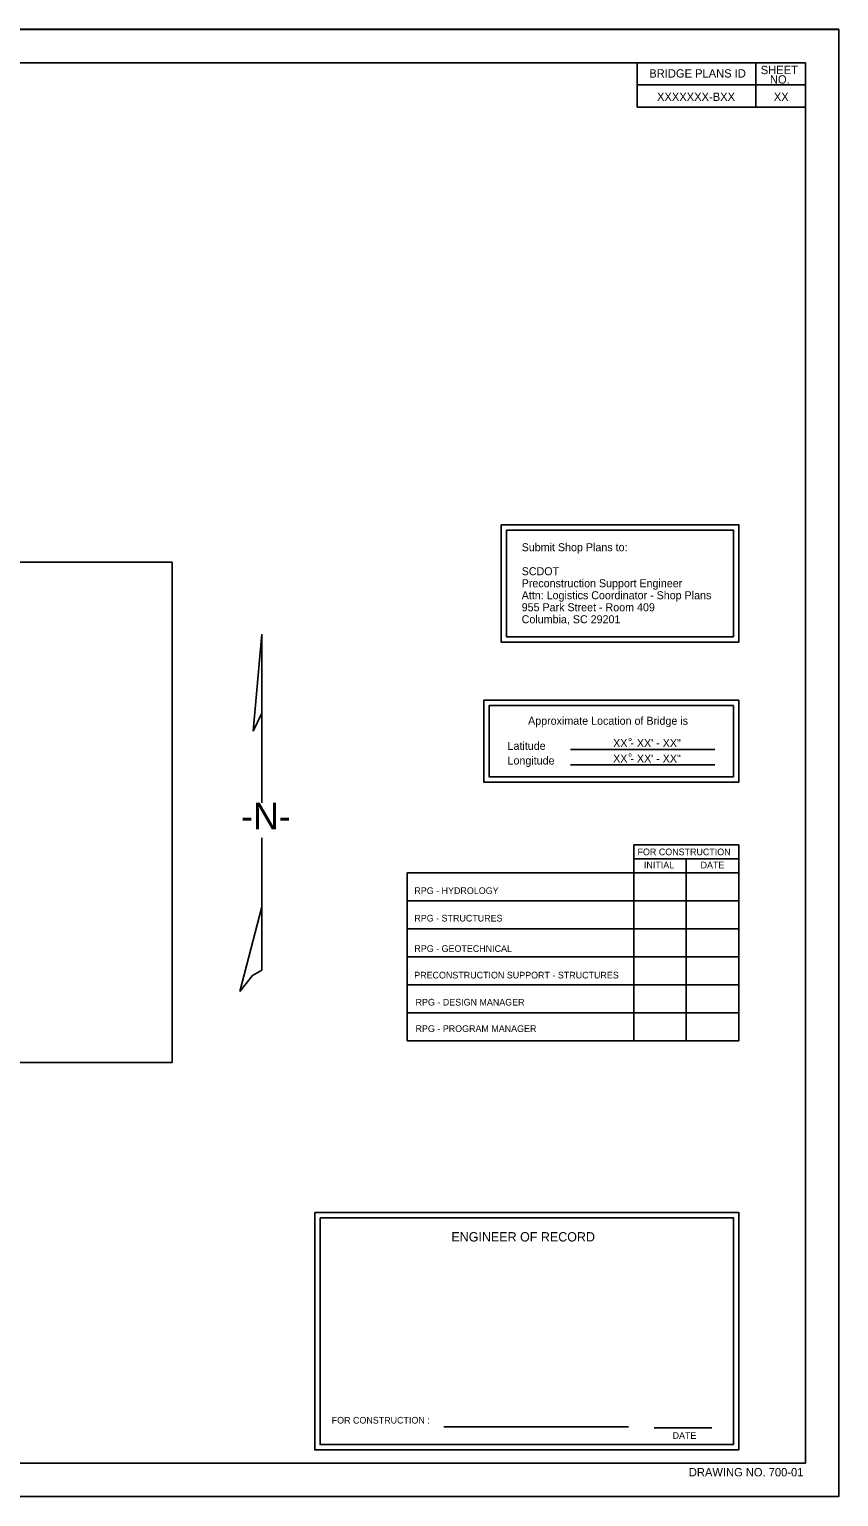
# Model space of a CAD drawing. Extents: x 841 to 4291, y -549 to 1701.
# Drawn here: x 1934 to 2541, y 601 to 1701 of the extents above; entities that cross this region are included whole.
import ezdxf

# ---------------------------------------------------------------- set-up
doc = ezdxf.new("R2010")
doc.units = 0
for name, color, linetype in [('BR_AUTO DIMENSION', 7, 'Continuous'), ('BR_BORDER LINES', 7, 'Continuous'), ('BR_REBAR', 7, 'Continuous'), ('BR_TEXT', 7, 'Continuous'), ('Default', 7, 'Continuous'), ('RD_SHT_IplotShp', 7, 'Continuous')]:
    doc.layers.add(name, color=color, linetype=linetype)

msp = doc.modelspace()

# ---------------------------------------------------------------- linework, layer by layer
at = {"layer": 'BR_BORDER LINES'}
for p, q in [((840.7, 1701.3), (2540.7, 1701.3)), ((2515.7, 1676.2), (940.7, 1676.2)), ((2389.6, 1642.9), (2389.6, 1676.2)), ((2474, 1676.2), (2474, 1676.2)), ((2478.6, 1642.9), (2478.6, 1676.2)), ((2494.8, 1676.2), (2494.8, 1676.2)), ((2515.7, 626.2), (2515.7, 1676.2)), ((2389.6, 1659.7), (2515.7, 1659.7)), ((2389.6, 1642.9), (2515.7, 1642.9)), ((940.7, 626.2), (2515.7, 626.2)), ((840.7, 601.3), (2540.7, 601.3))]:
    msp.add_line(p, q, dxfattribs=at)
at = {"layer": 'BR_REBAR'}
for p, q in [((1415.7, 1301.8), (2040.7, 1301.8)), ((2040.7, 1301.8), (2040.7, 926.8)), ((1415.7, 926.8), (2040.7, 926.8))]:
    msp.add_line(p, q, dxfattribs=at)
at = {"layer": 'Default'}
for p, q in [((2101.4, 1175.1), (2108.1, 1247.9)), ((2108.1, 1247.9), (2108.1, 1188.6)), ((2108.1, 1188.6), (2101.4, 1175.1)), ((2108.1, 1188.6), (2108.1, 1147.5)), ((2339.6, 1161.4), (2447.7, 1161.4)), ((2108.1, 1147.5), (2108.1, 1121.3)), ((2339.6, 1149.8), (2447.7, 1149.8)), ((2108.1, 1095.1), (2108.1, 1043.3)), ((2387, 1090), (2465.7, 1090)), ((2387, 943), (2387, 1090)), ((2465.7, 1090), (2465.7, 943)), ((2387, 1079.5), (2465.7, 1079.5)), ((2426.3, 1079.5), (2426.3, 943)), ((2217, 1069), (2465.7, 1069)), ((2217, 943), (2217, 1069)), ((2217, 1048), (2465.7, 1048)), ((2091.6, 979.9), (2108.1, 1043.3)), ((2108.1, 1043.3), (2108.1, 1035.5)), ((2108.1, 1035.5), (2108.1, 995.8)), ((2217, 1027), (2465.7, 1027)), ((2217, 1006), (2465.7, 1006)), ((2217, 985), (2465.7, 985)), ((2217, 964), (2465.7, 964)), ((2217, 943), (2465.7, 943)), ((2217, 943), (2459.5, 943)), ((2244.4, 653.5), (2383, 653.5)), ((2402.2, 652.9), (2445.6, 652.9))]:
    msp.add_line(p, q, dxfattribs=at)
for points in [[(2287.4, 1329.9), (2465.7, 1329.9), (2465.7, 1241.9), (2287.4, 1241.9)], [(2291.4, 1325.9), (2461.7, 1325.9), (2461.7, 1245.9), (2291.4, 1245.9)], [(2465.7, 1198.4), (2274.6, 1198.4), (2274.6, 1136.8), (2465.7, 1136.8)], [(2461.7, 1194.4), (2278.6, 1194.4), (2278.6, 1140.8), (2461.7, 1140.8)], [(2147.7, 814.3), (2465.7, 814.3), (2465.7, 636.3), (2147.7, 636.3)], [(2151.7, 810.3), (2461.7, 810.3), (2461.7, 640.3), (2151.7, 640.3)]]:
    msp.add_lwpolyline(points, close=True, dxfattribs=at)
msp.add_lwpolyline([(2108.1, 995.8), (2101, 991.9), (2091.6, 979.9)], dxfattribs=at)
at = {"layer": 'RD_SHT_IplotShp'}
msp.add_lwpolyline([(840.7, 1701.2), (2540.7, 1701.2), (2540.7, 601.2), (840.7, 601.2)], close=True, dxfattribs=at)

# ---------------------------------------------------------------- texts
at = {"layer": 'BR_AUTO DIMENSION'}
msp.add_text('DRAWING NO. 700-01', height=6.25, dxfattribs=at).set_placement((2428.3, 616.4))
at = {"layer": 'BR_TEXT'}
for s, p in [('SHEET', (2482.2, 1667.7)), ('BRIDGE PLANS ID', (2398.6, 1665.1)), ('NO.', (2489.1, 1660.6)), ('XXXXXXX-BXX', (2404.4, 1647.6)), ('XX', (2492, 1647.6))]:
    msp.add_text(s, height=6.25, dxfattribs=at).set_placement(p)
at = {"layer": 'Default'}
for s, height, p in [('Submit Shop Plans to:', 6, (2302.9, 1310)), ('SCDOT', 6, (2302.9, 1292)), ('Preconstruction Support Engineer', 6, (2302.9, 1283)), ('Attn: Logistics Coordinator - Shop Plans', 6, (2302.9, 1274)), ('955 Park Street - Room 409', 6, (2302.9, 1265)), ('Columbia, SC 29201', 6, (2302.9, 1256)), ('Approximate Location of Bridge is', 6, (2307.7, 1179.9)), ('Latitude', 6, (2292.3, 1161.1)), ('XX - XX\' - XX"', 6, (2371.5, 1163.2)), ('%%d', 6, (2382.6, 1164)), ('Longitude', 6, (2292.3, 1150.1)), ('XX - XX\' - XX"', 6, (2371.5, 1151.6)), ('%%d', 6, (2382.6, 1152.4)), ('-N-', 20, (2092.5, 1101.4)), ('FOR CONSTRUCTION', 5, (2389.8, 1082.1)), ('INITIAL', 5, (2394.6, 1072.2)), ('DATE', 5, (2437.1, 1072.2)), ('RPG - HYDROLOGY ', 5, (2222.4, 1053)), ('RPG - STRUCTURES', 5, (2222.4, 1032.4)), ('RPG - GEOTECHNICAL', 5, (2222.4, 1009.6)), ('PRECONSTRUCTION SUPPORT - STRUCTURES', 5, (2222.3, 989.7)), ('RPG - DESIGN MANAGER', 5, (2223.3, 969.4)), ('RPG - PROGRAM MANAGER', 5, (2223.3, 949.6)), ('ENGINEER OF RECORD', 7, (2250.2, 792.5)), ('FOR CONSTRUCTION :', 5, (2160.4, 656)), ('DATE', 5, (2416.1, 644.5))]:
    msp.add_text(s, height=height, dxfattribs=at).set_placement(p)

doc.saveas('drawing.dxf')
